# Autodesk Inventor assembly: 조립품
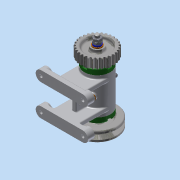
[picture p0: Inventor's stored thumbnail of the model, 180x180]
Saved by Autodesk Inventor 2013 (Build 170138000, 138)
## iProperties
Created: 2015-11
Part Number: 조립품
Document SubType Name: Assembly
Designer: user-11
Author: user-11
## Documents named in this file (16)
- C:\Users\user-11\Desktop\451109V1035\조립품.iam
- C:\Users\user-11\Desktop\451109V1035\V벨트풀리.ipt
- C:\Users\user-11\Desktop\451109V1035\너트 M 8.ipt
- C:\Users\user-11\Desktop\451109V1035\니플 M 6 x 0.75.ipt
- C:\Users\user-11\Desktop\451109V1035\베어링 15 x 32 x 9.ipt
- C:\Users\user-11\Desktop\451109V1035\본체.ipt
- C:\Users\user-11\Desktop\451109V1035\볼트 M 6 x 8.ipt
- C:\Users\user-11\Desktop\451109V1035\볼트 M4 x 12.ipt
- C:\Users\user-11\Desktop\451109V1035\스퍼기어.ipt
- C:\Users\user-11\Desktop\451109V1035\스프링와셔 8.ipt
- C:\Users\user-11\Desktop\451109V1035\오일 실 15 25 7.ipt
- C:\Users\user-11\Desktop\451109V1035\와셔 6x11.5.ipt
- C:\Users\user-11\Desktop\451109V1035\와셔 8x17.ipt
- C:\Users\user-11\Desktop\451109V1035\축.ipt
- C:\Users\user-11\Desktop\451109V1035\커버.ipt
- C:\Users\user-11\Desktop\451109V1035\키 3 x 3 x 12.ipt
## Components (8 placed, 3 different names)
1. V벨트풀리:1
2. KS B 2023 6002 - 15 x 32 x 9:1
3. KS B 2023 6002 - 15 x 32 x 9:2
4. ISO 4762 M4 x 12:2
5. ISO 4762 M4 x 12:1
6. ISO 4762 M4 x 12:3
7. ISO 4762 M4 x 12:4
8. ISO 4762 M4 x 12:5
